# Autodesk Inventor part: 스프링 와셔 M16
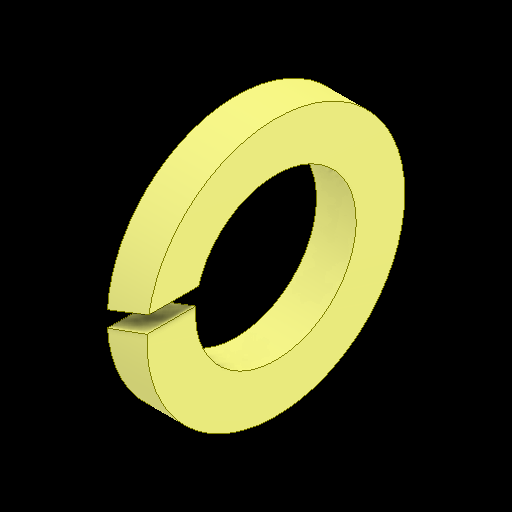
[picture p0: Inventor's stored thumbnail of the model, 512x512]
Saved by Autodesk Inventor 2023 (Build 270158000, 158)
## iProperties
Created: 2025-01
Part Number: 스프링 와셔 M16
Material: 강철, 연강
Description: 스프링 잠금 와셔
Document SubType Name: Modeling
Designer: 강의실01
Density: 7.85 g/cm^3
Appearance: 기본값
Author: jhkim
Sending System: Autodesk Inventor 2025
Preprocessor: ST-DEVELOPER v20
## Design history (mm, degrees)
feature "Solid1"
node "솔리드1"
